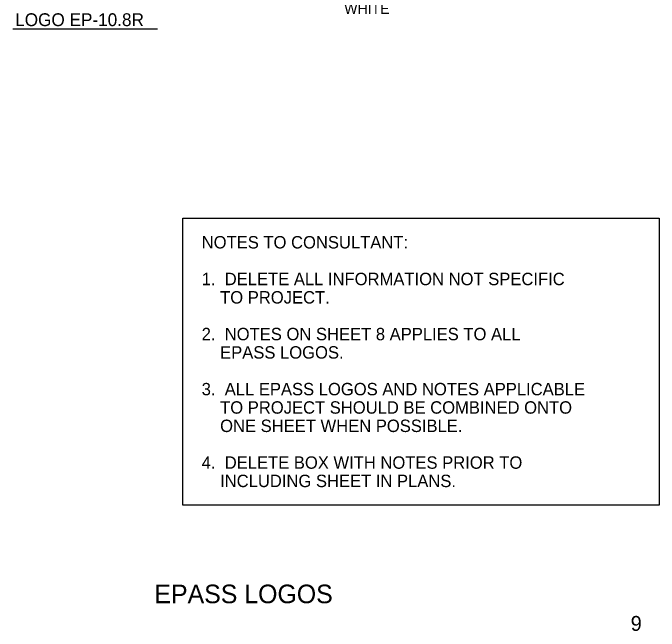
# Model space of a CAD drawing. Extents: x 10268197 to 10269179, y 2141503 to 2142677.
# Drawn here: x 10268693.31 to 10268736.74, y 2141952.64 to 2141994.18 of the extents above; entities that cross this region are included whole.
import ezdxf

# ---------------------------------------------------------------- set-up
doc = ezdxf.new("R2010")
doc.units = 0
for name, color, linetype in [('1', 7, 'Continuous'), ('21', 7, 'Continuous'), ('TextAlert', 7, 'Continuous'), ('TextMisc', 7, 'Continuous'), ('TextShtNo', 7, 'Continuous')]:
    doc.layers.add(name, color=color, linetype=linetype)

msp = doc.modelspace()

# ---------------------------------------------------------------- linework, layer by layer
at = {"layer": '21'}
msp.add_line((10268693.315, 2141993.117), (10268703.027, 2141993.117), dxfattribs=at)
at = {"layer": 'TextAlert'}
msp.add_lwpolyline([(10268704.725, 2141980.395), (10268736.74, 2141980.395), (10268736.74, 2141961.108), (10268704.725, 2141961.108)], close=True, dxfattribs=at)

# ---------------------------------------------------------------- texts
at = {"layer": '1'}
for s, height, p in [('WHITE', 0.7047, (10268715.584, 2141994.107)), ('LOGO EP-10.8R', 0.8624, (10268693.466, 2141993.29))]:
    msp.add_text(s, height=height, dxfattribs=at).set_placement(p)
at = {"layer": 'TextAlert'}
for s, p in [('NOTES TO CONSULTANT:', (10268706.001, 2141978.351)), ('1.  DELETE ALL INFORMATION NOT SPECIFIC ', (10268706.001, 2141975.885)), ('    TO PROJECT.', (10268706.001, 2141974.651)), ('2.  NOTES ON SHEET 8 APPLIES TO ALL', (10268706.001, 2141972.185)), ('    EPASS LOGOS.', (10268706.001, 2141970.951)), ('3.  ALL EPASS LOGOS AND NOTES APPLICABLE', (10268706.001, 2141968.485)), ('    TO PROJECT SHOULD BE COMBINED ONTO', (10268706.001, 2141967.251)), ('    ONE SHEET WHEN POSSIBLE.', (10268706.001, 2141966.018)), ('4.  DELETE BOX WITH NOTES PRIOR TO ', (10268706.001, 2141963.551)), ('    INCLUDING SHEET IN PLANS.', (10268706.001, 2141962.318))]:
    msp.add_text(s, height=0.83333, dxfattribs=at).set_placement(p)
at = {"layer": 'TextMisc'}
msp.add_text('         EPASS LOGOS           ', height=1.25, rotation=360, dxfattribs=at).set_placement((10268698.645, 2141954.516))
at = {"layer": 'TextShtNo'}
msp.add_text('9', height=1, rotation=360, dxfattribs=at).set_placement((10268734.831, 2141952.659))

doc.saveas('drawing.dxf')
